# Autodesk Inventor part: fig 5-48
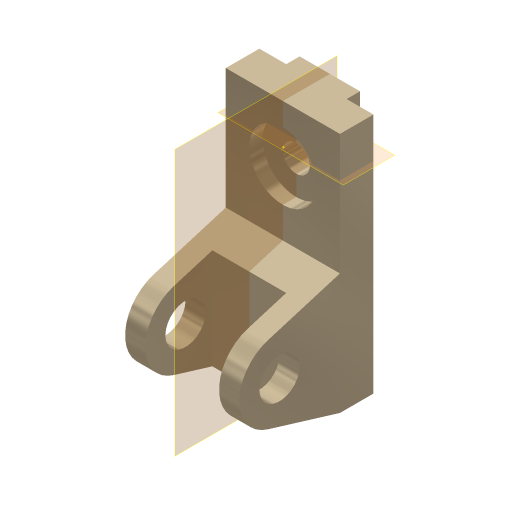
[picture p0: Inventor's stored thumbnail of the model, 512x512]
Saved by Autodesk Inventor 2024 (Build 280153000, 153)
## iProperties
Shininess: 65.0
Angle Display Precision: 2
Document Length Units: 11269
Document Angle Units: 11279
Document Time Units: 11290
Document Mass Units: 11283
Document Length Units Precision: 3
Document Angle Units Precision: 2
Created: 2001-11
Part Number: fig 5-48
Document SubType Name: Modeling
Designer: Renu Muthoo
Density: 1 g/cm^3
Material: Generic
Appearance: Metal-Titanium (Polished)
Density: 0.0
Volumn: 0.0
Area: 0.0
PropertySet Name: Model Information
Control State: 0
Master: False
Checked Out: False
Author: Renu Muthoo
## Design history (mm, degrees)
sketch "Sketch2"
  geometry: L1 (33.257, 104.664)-(33.257, -75.336); L2 (33.257, -75.336)-(8.257, -75.336); L3 (8.257, -75.336)-(-45.451, -59.045); L4 (-45.451, -1.628)-(8.257, 14.664); L5 (8.257, 14.664)-(8.257, 104.664); L6 (8.257, 104.664)-(33.257, 104.664); C1 r 15 at (-36.743, -30.336); A1 r 30 centre (-36.743, -30.336) between (-45.451, -1.628) and (-45.451, -59.045)
  constraints: 12 end point, 2 centre point, 2 equal length, 2 parallel, 2 point on circle, 2 tangent, 1 coincident, 1 perpendicular, 1 vertical
  dimensions: "d0" = 180 distance of L1.start L1.end; "d1" = 30 radius of A1; "d2" = 25 distance of L5.end L1.start; "d3" = 45 distance from line of L2 A1.centre; "d4" = 70 distance from line of L1 A1.centre; "d5" = 30 diameter of C1
extrude "Extrusion1" new body sketch "Sketch2" distance "d6" = 85; taper "d7" = 0 deg
workplane "Work Plane1"
sketch "Sketch3"
  geometry: L1 (15, 62.364)-(70, 62.364); L2 (70, 62.364)-(70, -52.386); L3 (70, -52.386)-(15, -52.386); L4 (15, -52.386)-(15, 62.364); L5 (0, -45)-(0, -28.708) reference
  constraints: 8 end point, 2 parallel, 1 horizontal, 1 perpendicular
  dimensions: "d8" = 55 distance of L1.start L1.end; "d9" = 15 distance between parallel lines of L5 L4
extrude "Extrusion2" cut sketch "Sketch3" distance "d10" = 50; taper "d11" = 0 deg
sketch "Sketch4"
  geometry: L1 (0, 25)-(85, 25) reference; L2 (0, 0)-(0, 25) reference; L3 (20, 25)-(65, 25); L4 (65, 25)-(65, 35); L5 (65, 35)-(20, 35); L6 (20, 35)-(20, 25)
  constraints: 8 end point, 2 parallel, 1 horizontal, 1 perpendicular, 1 point on line
  dimensions: "d12" = 45 distance of L4.end L5.end; "d13" = 10 distance of L3.end L4.end; "d14" = 20 distance between parallel lines of L2 L6
extrude "Extrusion3" join sketch "Sketch4" stored distance "d15" = 50; taper "d16" = 0 deg
sketch "Sketch5"
  geometry: L1 (85, 0)-(85, 90) reference; L2 (0, 90)-(85, 90) reference; 1 further point
  dimensions: "d17" = 42 distance from line of L2 point (42.5, 48); "d18" = 42.5 distance from line of L1 point (42.5, 48)
hole "Hole1" sketch "Sketch5" diameter "d19" = 20; stored, may be unused: countersink angle "d23" = 82 deg, drill point angle "d25" = 118 deg; dims "d20" = 6, "d21" = 50, "d22" = 10, "d24" = 8
workpoint "Work Point9"
  workplane "Work Plane8"
  workplane "Work Plane12"
body "Solid1"
node "Sketch1"
